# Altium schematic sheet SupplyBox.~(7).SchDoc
size B; SheetNumber: 1; SheetTotal: 1
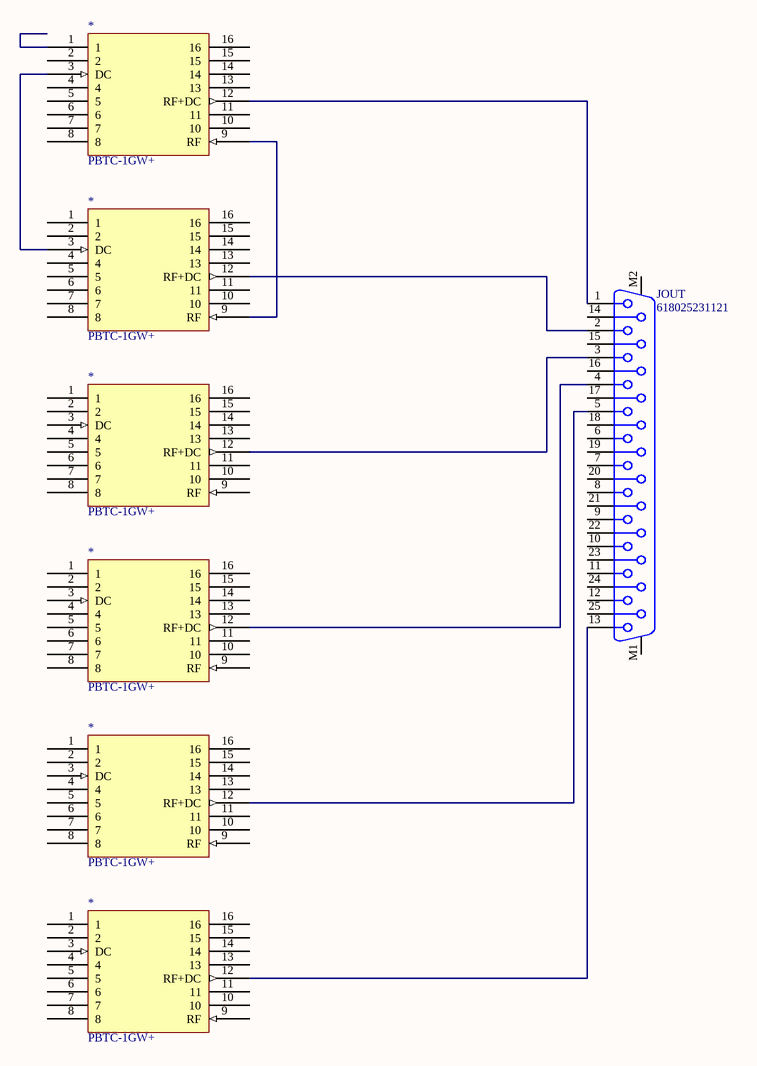
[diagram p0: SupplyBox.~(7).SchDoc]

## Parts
(Parts that share a designator on the sheet are numbered #1, #2 ... from top to bottom, then left to right.)
*#1  PBTC-1GW+  [PBTC-1GW+]
*#2  PBTC-1GW+  [PBTC-1GW+]
*#3  PBTC-1GW+  [PBTC-1GW+]
*#4  PBTC-1GW+  [PBTC-1GW+]
*#5  PBTC-1GW+  [PBTC-1GW+]
*#6  PBTC-1GW+  [PBTC-1GW+]
JOUT  618025231121  [618025231121]

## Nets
Net*#1_3: *#1.3(DC) *#2.3(DC)
Net*#1_9: *#1.9(RF) *#2.9(RF)
Net*#1_12: *#1.12(RF+DC) JOUT.1
Net*#2_12: *#2.12(RF+DC) JOUT.2
Net*#3_12: *#3.12(RF+DC) JOUT.3
Net*#4_12: *#4.12(RF+DC) JOUT.4
Net*#5_12: *#5.12(RF+DC) JOUT.5
Net*#6_12: *#6.12(RF+DC) JOUT.13

Not connected (* = marked no-connect by the designer): *#1 1 2 4 5 6 7 8 10 11 13 14 15 16; *#2 1 2 4 5 6 7 8 10 11 13 14 15 16; *#3 1 2 3(DC) 4 5 6 7 8 9(RF) 10 11 13 14 15 16; *#4 1 2 3(DC) 4 5 6 7 8 9(RF) 10 11 13 14 15 16; *#5 1 2 3(DC) 4 5 6 7 8 9(RF) 10 11 13 14 15 16; *#6 1 2 3(DC) 4 5 6 7 8 9(RF) 10 11 13 14 15 16; JOUT 6 7 8 9 10 11 12 14 15 16 17 18 19 20 21 22 23 24 25 M1 M2

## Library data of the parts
*#1-*#6 = CMP-00025-00003-1: Monitor TEE DC Block, 0.1MHz Min, 1000MHz Max, 1dB Insertion Loss-Max
JOUT = CMP-1502-00202-2: NexarPartId: 18818207; Pitch: 2.77mm; Operating Supply Voltage: 125V; Gender: Female; Insulation Resistance: 5GΩ; Contact Resistance: 30mΩ; Current Rating: 3A; Number of Contacts: 25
